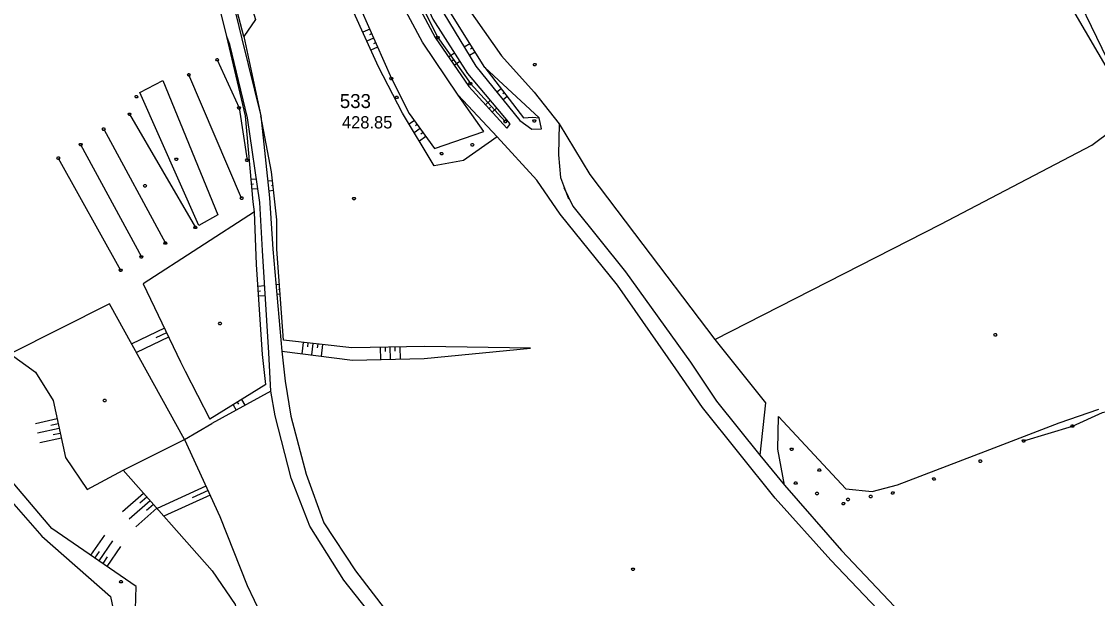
# Model space of a CAD drawing. Extents: x -664960 to -662754, y -993849 to -991145.
# Drawn here: x -663555.7 to -663293.4, y -993173.7 to -993033.1 of the extents above; entities that cross this region are included whole.
import ezdxf

# ---------------------------------------------------------------- set-up
doc = ezdxf.new("R2010")
doc.units = 0
for name, color, linetype in [('Vrstva 1', 7, 'Continuous'), ('Vrstva 13', 7, 'Continuous'), ('Vrstva 27', 7, 'Continuous'), ('Vrstva 63', 7, 'Continuous'), ('Vrstva 8', 7, 'Continuous')]:
    doc.layers.add(name, color=color, linetype=linetype)

msp = doc.modelspace()

# ---------------------------------------------------------------- linework, layer by layer
at = {"layer": 'Vrstva 13'}
for points in [[(-663430.387, -993043.291), (-663430.207, -993043.591), (-663430.387, -993043.891), (-663430.747, -993043.891), (-663430.927, -993043.591), (-663430.747, -993043.291), (-663430.387, -993043.291)], [(-663517.748, -993066.373), (-663517.568, -993066.673), (-663517.748, -993066.973), (-663518.108, -993066.973), (-663518.288, -993066.673), (-663518.108, -993066.373), (-663517.748, -993066.373)], [(-663525.362, -993072.832), (-663525.182, -993073.132), (-663525.362, -993073.432), (-663525.722, -993073.432), (-663525.902, -993073.132), (-663525.722, -993072.832), (-663525.362, -993072.832)], [(-663474.427, -993075.96), (-663474.247, -993076.26), (-663474.427, -993076.56), (-663474.787, -993076.56), (-663474.967, -993076.26), (-663474.787, -993075.96), (-663474.427, -993075.96)], [(-663507.072, -993106.416), (-663506.892, -993106.716), (-663507.072, -993107.016), (-663507.432, -993107.016), (-663507.612, -993106.716), (-663507.432, -993106.416), (-663507.072, -993106.416)], [(-663318.17, -993109.156), (-663317.99, -993109.456), (-663318.17, -993109.756), (-663318.53, -993109.756), (-663318.71, -993109.456), (-663318.53, -993109.156), (-663318.17, -993109.156)], [(-663535.22, -993125.181), (-663535.04, -993125.481), (-663535.22, -993125.781), (-663535.58, -993125.781), (-663535.76, -993125.481), (-663535.58, -993125.181), (-663535.22, -993125.181)], [(-663366.791, -993145.297), (-663366.611, -993145.597), (-663366.791, -993145.897), (-663367.151, -993145.897), (-663367.331, -993145.597), (-663367.151, -993145.297), (-663366.791, -993145.297)], [(-663406.456, -993166.312), (-663406.276, -993166.612), (-663406.456, -993166.912), (-663406.816, -993166.912), (-663406.996, -993166.612), (-663406.816, -993166.312), (-663406.456, -993166.312)]]:
    msp.add_lwpolyline(points, dxfattribs=at)
at = {"layer": 'Vrstva 27'}
msp.add_line((-663436.64, -993058.03), (-663437.38, -993059.1), dxfattribs=at)
for points in [[(-663488.658, -992771.319), (-663486.041, -992777.124), (-663484.479, -992778.312), (-663480.688, -992780.627), (-663479.797, -992784.051), (-663480.225, -992798.776), (-663480.106, -992812.528), (-663479.191, -992846.153), (-663478.672, -992868.89), (-663478.583, -992881.904), (-663478.082, -992895.396), (-663476.627, -992914.637), (-663474.815, -992928.231), (-663470.676, -992951.637), (-663468.34, -992962.956), (-663456.927, -993007.431), (-663447.138, -993029.424), (-663438.677, -993041.464), (-663430.737, -993050.315), (-663424.65, -993058.054), (-663424.821, -993065.561), (-663424.273, -993071.083), (-663422.364, -993076.277)], [(-663493.095, -992883.033), (-663492.196, -992861.424), (-663492.956, -992822.595), (-663492.609, -992797.023), (-663492.331, -992783.259), (-663491.101, -992775.678), (-663489.833, -992782.642), (-663491.019, -992797.262), (-663489.769, -992835.934), (-663490.477, -992858.663), (-663491.12, -992880.1), (-663489.906, -992896.409), (-663487.878, -992911.561), (-663485.118, -992929.166), (-663480.702, -992952.347), (-663470.868, -992991.635), (-663466.023, -993009.002), (-663455.437, -993032.516), (-663446.928, -993045.767), (-663436.64, -993058.03)], [(-663292.32, -993232.82), (-663314.09, -993212.62), (-663328.7, -993196.3), (-663343.76, -993179.73), (-663358.38, -993164.43), (-663372, -993149.25), (-663389.69, -993127.17), (-663396.18, -993117.78), (-663410.43, -993097.33), (-663424.37, -993080.01), (-663430.1, -993071.8), (-663439.74, -993061.19), (-663449.23, -993051.04), (-663457.96, -993038.08), (-663463.23, -993028.27), (-663471.77, -993006.86), (-663476.02, -992992.74), (-663480.89, -992974.93), (-663481.39, -992971.3), (-663486.69, -992951.1), (-663491.43, -992929.63), (-663493.61, -992914.38), (-663496.5, -992893.77)], [(-663490.26, -992913.59), (-663487.91, -992929.15), (-663483.47, -992949.71), (-663477.64, -992974.17), (-663473.27, -992991.48), (-663468.86, -993005.23), (-663460.26, -993026.75), (-663454.82, -993037.02), (-663446.62, -993048.94), (-663437.38, -993059.1)], [(-663525.07, -992922.44), (-663521.64, -992937.94), (-663518.46, -992961.72), (-663514.64, -992984.19), (-663509.85, -993004.83), (-663501.96, -993037.29), (-663497.29, -993056.07), (-663495.2, -993076.09), (-663494.44, -993088.61), (-663492.24, -993113.44), (-663491.4, -993120.78), (-663490.02, -993129.31), (-663486.29, -993143.39), (-663482, -993155.26), (-663474.22, -993166.96), (-663462.98, -993181.7), (-663450.36, -993195.84), (-663435.28, -993211.34), (-663418, -993227.21), (-663404.31, -993240.04), (-663391.6, -993253.92), (-663379.85, -993267.71)], [(-663381.88, -993269.82), (-663387.32, -993265.33), (-663393.79, -993257), (-663407.95, -993241.48), (-663421.02, -993229.28), (-663438.16, -993213.52), (-663452.44, -993198.54), (-663465.76, -993183.63), (-663477.14, -993169.29), (-663485.35, -993156.12), (-663489.97, -993144.37), (-663493.8, -993129.17), (-663494.9, -993123.17), (-663495.36, -993113.85), (-663496.9, -993088.93), (-663497.54, -993077.21), (-663500.56, -993056.55), (-663504.87, -993038.7), (-663505.62, -993036.77), (-663513.31, -993005.37), (-663518.03, -992984.98), (-663521.99, -992961.69), (-663525.31, -992938.73), (-663526.62, -992930.83)], [(-663452.727, -993031.168), (-663444.935, -993044.005), (-663434.228, -993057.192)], [(-663434.228, -993057.192), (-663431.273, -993059.365), (-663428.963, -993059.284), (-663429.498, -993056.55), (-663442.777, -993044.277), (-663451.02, -993031.047)], [(-663423.48, -993073.55), (-663421.28, -993078.11), (-663408.44, -993094.13), (-663392.6, -993116.09), (-663386.27, -993125.65), (-663375.681, -993138.823)], [(-663375.681, -993138.823), (-663369.729, -993146.08), (-663355.79, -993162.06), (-663341.44, -993177.26), (-663326.1, -993194.37), (-663310.82, -993210.78), (-663290.07, -993230.27), (-663283.91, -993235.59), (-663283.15, -993228.16)]]:
    msp.add_lwpolyline(points, dxfattribs=at)
at = {"layer": 'Vrstva 63'}
for p, q in [((-663470.8, -993034.977), (-663472.46, -993035.707)), ((-663470.317, -993036.075), (-663470.866, -993036.317)), ((-663501.47, -993036.75), (-663497.29, -993056.07)), ((-663469.834, -993037.174), (-663471.472, -993037.894)), ((-663469.351, -993038.272), (-663469.893, -993038.511)), ((-663446.381, -993038.493), (-663447.759, -993039.352)), ((-663468.868, -993039.371), (-663470.484, -993040.081)), ((-663451.577, -993041.734), (-663450.149, -993040.751)), ((-663445.112, -993040.53), (-663446.514, -993041.404)), ((-663445.746, -993039.511), (-663446.209, -993039.8)), ((-663450.897, -993042.723), (-663450.432, -993042.403)), ((-663450.217, -993043.711), (-663448.851, -993042.772)), ((-663502.02, -993076.15), (-663514.87, -993046.09)), ((-663438.756, -993049.486), (-663439.819, -993050.306)), ((-663438.023, -993050.436), (-663438.369, -993050.703)), ((-663438.023, -993050.436), (-663438.369, -993050.703)), ((-663437.29, -993051.386), (-663438.305, -993052.17)), ((-663437.29, -993051.386), (-663438.305, -993052.17)), ((-663442.572, -993053.391), (-663441.415, -993052.339)), ((-663441.765, -993054.279), (-663441.391, -993053.939)), ((-663440.957, -993055.166), (-663439.871, -993054.179)), ((-663529.33, -993055.69), (-663513.29, -993083.28)), ((-663459.906, -993057.225), (-663461.179, -993058.142)), ((-663535.6, -993059.32), (-663520.59, -993087.1)), ((-663458.504, -993059.173), (-663459.939, -993060.207)), ((-663459.205, -993058.199), (-663459.656, -993058.524)), ((-663457.102, -993061.122), (-663458.7, -993062.272)), ((-663457.803, -993060.148), (-663458.308, -993060.511)), ((-663541.25, -993063.1), (-663526.45, -993090.48)), ((-663546.7, -993066.39), (-663531.49, -993093.72)), ((-663499.705, -993071.512), (-663498.389, -993071.399)), ((-663499.602, -993072.708), (-663499.14, -993072.668)), ((-663494.455, -993071.902), (-663495.624, -993072.032)), ((-663494.323, -993073.095), (-663494.714, -993073.138)), ((-663499.499, -993073.903), (-663498.042, -993073.778)), ((-663494.19, -993074.287), (-663495.374, -993074.419)), ((-663526.01, -993097.07), (-663526.01, -993097.07)), ((-663498.033, -993097.589), (-663496.372, -993097.477)), ((-663497.952, -993098.787), (-663497.401, -993098.749)), ((-663492.793, -993097.18), (-663493.675, -993097.243)), ((-663492.707, -993098.377), (-663492.994, -993098.397)), ((-663497.872, -993099.984), (-663496.224, -993099.873)), ((-663492.622, -993099.574), (-663493.463, -993099.634)), ((-663520.842, -993107.877), (-663528.773, -993111.669)), ((-663520.325, -993108.96), (-663522.944, -993110.212)), ((-663519.807, -993110.042), (-663527.61, -993113.773)), ((-663487.046, -993111.308), (-663487.356, -993114.065)), ((-663485.853, -993111.442), (-663485.957, -993112.366)), ((-663484.661, -993111.576), (-663484.975, -993114.37)), ((-663483.468, -993111.711), (-663483.574, -993112.647)), ((-663482.276, -993111.845), (-663482.594, -993114.674)), ((-663465.849, -993112.488), (-663465.797, -993115.435)), ((-663464.649, -993112.467), (-663464.632, -993113.446)), ((-663463.449, -993112.446), (-663463.398, -993115.379)), ((-663468.248, -993112.53), (-663468.197, -993115.491)), ((-663467.049, -993112.509), (-663467.031, -993113.493)), ((-663496.08, -993121.57), (-663509.78, -993130.06)), ((-663494.9, -993123.17), (-663509.29, -993131.09)), ((-663502.046, -993125.267), (-663501.198, -993126.636)), ((-663504.086, -993126.532), (-663503.303, -993127.795)), ((-663503.066, -993125.899), (-663502.795, -993126.338)), ((-663546.972, -993129.971), (-663552.247, -993131.124)), ((-663546.46, -993132.315), (-663551.735, -993133.468)), ((-663546.716, -993131.143), (-663548.472, -993131.527)), ((-663515.89, -993134.97), (-663509.29, -993131.09)), ((-663545.947, -993134.66), (-663551.222, -993135.813)), ((-663546.203, -993133.488), (-663547.96, -993133.872)), ((-663510.701, -993146.343), (-663522.627, -993151.785)), ((-663525.897, -993148.104), (-663531.008, -993152.643)), ((-663525.1, -993149.001), (-663526.802, -993150.512)), ((-663509.704, -993148.527), (-663520.96, -993153.662)), ((-663510.202, -993147.435), (-663514.062, -993149.196)), ((-663524.303, -993149.898), (-663529.414, -993154.437)), ((-663522.709, -993151.693), (-663527.82, -993156.232)), ((-663523.506, -993150.795), (-663525.208, -993152.307)), ((-663538.742, -993163.188), (-663535.38, -993158.305)), ((-663536.765, -993164.549), (-663533.404, -993159.666)), ((-663537.754, -993163.869), (-663536.634, -993162.243)), ((-663534.788, -993165.91), (-663531.427, -993161.027)), ((-663535.777, -993165.23), (-663534.657, -993163.603))]:
    msp.add_line(p, q, dxfattribs=at)
for points in [[(-663284.547, -993055.601), (-663299.44, -993030.172), (-663309.766, -993014.643), (-663318.448, -993000.715), (-663328.04, -992979.81), (-663341.459, -992959.362), (-663349.326, -992940.508), (-663361.239, -992916.927), (-663363.985, -992907.073), (-663365.563, -992896.567), (-663365.153, -992888.878), (-663367.39, -992872.717), (-663367.977, -992865.006), (-663366.113, -992853.429)], [(-663502.72, -992895.66), (-663500.68, -992911.72), (-663499.46, -992928.5), (-663496.04, -992950.81), (-663489.58, -992971.15), (-663490.24, -992973.92), (-663484.12, -992998.39), (-663477.64, -993017.5), (-663472.94, -993030.11), (-663465.51, -993047.01), (-663461.14, -993055.51), (-663454.98, -993064.07), (-663443.01, -993059.86), (-663449.23, -993051.04)], [(-663488.98, -992912.94), (-663486.69, -992929.18), (-663482.79, -992948.58), (-663476.6, -992971.57), (-663472.24, -992991.59), (-663467.82, -993006.73), (-663460.34, -993024.66), (-663454.22, -993037), (-663446.26, -993048.23), (-663437.77, -993057.47)], [(-663528.28, -993190.19), (-663527.67, -993170.81), (-663548.24, -993156.65), (-663567.3, -993134.31), (-663574.62, -993124.52), (-663575.76, -993123.74), (-663583.3, -993106.69), (-663584.43, -993103.48), (-663591.54, -993086.62), (-663586.94, -993078.34), (-663586.28, -993073.08), (-663589.41, -993059.58), (-663591.86, -993055.15), (-663591.76, -993041.53), (-663588.44, -993036.54), (-663581.11, -993025.88), (-663583.2, -993018.84), (-663591.05, -993014.06), (-663610.46, -992999.53), (-663616.86, -992987.81), (-663623.87, -992975.97), (-663633.54, -992963.29)], [(-663439.74, -993061.19), (-663447.96, -993066.95), (-663455.1, -993068.27), (-663462.83, -993055.39), (-663468.65, -993044.14), (-663477.89, -993023.69), (-663486.03, -992998.86), (-663489.83, -992986.14), (-663509.79, -992996.09), (-663498.66, -993032.57), (-663501.47, -993036.75), (-663509.85, -993004.83)], [(-663246.904, -993114.369), (-663255.353, -993101.711), (-663256.984, -993088.158), (-663273.685, -993069.79), (-663284.547, -993055.601), (-663300.016, -993023.681), (-663309.766, -993014.643)], [(-663477.64, -993017.5), (-663472.94, -993030.11), (-663465.51, -993047.01)], [(-663496.08, -993121.57), (-663496.91, -993114.26), (-663498.39, -993092.29), (-663498.87, -993079.49), (-663499.23, -993077.04), (-663501.03, -993056.09), (-663505.62, -993036.77)], [(-663454.04, -993036.7), (-663453.86, -993037), (-663454.04, -993037.3), (-663454.4, -993037.3), (-663454.58, -993037), (-663454.4, -993036.7), (-663454.04, -993036.7)], [(-663507.79, -993042.09), (-663507.61, -993042.39), (-663507.79, -993042.69), (-663508.15, -993042.69), (-663508.33, -993042.39), (-663508.15, -993042.09), (-663507.79, -993042.09)], [(-663507.97, -993042.39), (-663502.64, -993054.16), (-663500.68, -993066.87)], [(-663442.777, -993044.277), (-663433.284, -993056.576), (-663431.053, -993056.394), (-663429.498, -993056.55)], [(-663514.69, -993045.79), (-663514.51, -993046.09), (-663514.69, -993046.39), (-663515.05, -993046.39), (-663515.23, -993046.09), (-663515.05, -993045.79), (-663514.69, -993045.79)], [(-663465.33, -993046.71), (-663465.15, -993047.01), (-663465.33, -993047.31), (-663465.69, -993047.31), (-663465.87, -993047.01), (-663465.69, -993046.71), (-663465.33, -993046.71)], [(-663526.78, -993050.43), (-663521.21, -993047.47), (-663507.81, -993080.19), (-663512.45, -993082.81), (-663526.78, -993050.43)], [(-663446.08, -993047.93), (-663445.9, -993048.23), (-663446.08, -993048.53), (-663446.44, -993048.53), (-663446.62, -993048.23), (-663446.44, -993047.93), (-663446.08, -993047.93)], [(-663527.47, -993051.11), (-663527.29, -993051.41), (-663527.47, -993051.71), (-663527.83, -993051.71), (-663528.01, -993051.41), (-663527.83, -993051.11), (-663527.47, -993051.11)], [(-663502.46, -993053.86), (-663502.28, -993054.16), (-663502.46, -993054.46), (-663502.82, -993054.46), (-663503, -993054.16), (-663502.82, -993053.86), (-663502.46, -993053.86)], [(-663529.15, -993055.39), (-663528.97, -993055.69), (-663529.15, -993055.99), (-663529.51, -993055.99), (-663529.69, -993055.69), (-663529.51, -993055.39), (-663529.15, -993055.39)], [(-663492.24, -993113.44), (-663474.97, -993115.65), (-663457.49, -993115.24), (-663431.634, -993112.752), (-663457.36, -993112.34), (-663475.13, -993112.65), (-663491.82, -993110.77), (-663493.41, -993088.56), (-663493.4, -993081.42), (-663494.7, -993069.69), (-663497.29, -993056.07)], [(-663437.59, -993057.17), (-663437.41, -993057.47), (-663437.59, -993057.77), (-663437.95, -993057.77), (-663438.13, -993057.47), (-663437.95, -993057.17), (-663437.59, -993057.17)], [(-663430.49, -993057.014), (-663430.31, -993057.314), (-663430.49, -993057.614), (-663430.85, -993057.614), (-663431.03, -993057.314), (-663430.85, -993057.014), (-663430.49, -993057.014)], [(-663386.718, -993110.575), (-663331.567, -993082.506), (-663294.803, -993063.252), (-663284.547, -993055.601)], [(-663535.42, -993059.02), (-663535.24, -993059.32), (-663535.42, -993059.62), (-663535.78, -993059.62), (-663535.96, -993059.32), (-663535.78, -993059.02), (-663535.42, -993059.02)], [(-663424.65, -993058.054), (-663417.136, -993070.372), (-663406.273, -993084.722), (-663386.718, -993110.575), (-663374.342, -993126.019), (-663375.681, -993138.823)], [(-663541.07, -993062.8), (-663540.89, -993063.1), (-663541.07, -993063.4), (-663541.43, -993063.4), (-663541.61, -993063.1), (-663541.43, -993062.8), (-663541.07, -993062.8)], [(-663453.11, -993065), (-663452.93, -993065.3), (-663453.11, -993065.6), (-663453.47, -993065.6), (-663453.65, -993065.3), (-663453.47, -993065), (-663453.11, -993065)], [(-663445.6, -993062.85), (-663445.42, -993063.15), (-663445.6, -993063.45), (-663445.96, -993063.45), (-663446.14, -993063.15), (-663445.96, -993062.85), (-663445.6, -993062.85)], [(-663546.52, -993066.09), (-663546.34, -993066.39), (-663546.52, -993066.69), (-663546.88, -993066.69), (-663547.06, -993066.39), (-663546.88, -993066.09), (-663546.52, -993066.09)], [(-663500.5, -993066.57), (-663500.32, -993066.87), (-663500.5, -993067.17), (-663500.86, -993067.17), (-663501.04, -993066.87), (-663500.86, -993066.57), (-663500.5, -993066.57)], [(-663588.73, -993072.01), (-663588.67, -993078.79), (-663591.54, -993086.62), (-663590.79, -993097.47), (-663587.28, -993107.16), (-663580.23, -993125.77), (-663578.42, -993128.41), (-663569.53, -993137.12), (-663550.67, -993158.56), (-663534, -993173.23), (-663531.62, -993184.53), (-663529.51, -993196.8), (-663524.27, -993210.22), (-663515.61, -993222.94), (-663503.03, -993237.27)], [(-663567.12, -993071.76), (-663567.81, -993074.85), (-663569.5, -993087.65), (-663569.75, -993094.71), (-663565.21, -993104.7), (-663558.45, -993114.09), (-663552.27, -993118.59), (-663547.96, -993125.45), (-663544.92, -993139.36), (-663539.64, -993147.19), (-663530.9, -993142.47), (-663509.15, -993166.96), (-663503.55, -993175.23), (-663501.36, -993184.63), (-663489.77, -993200.53), (-663484.02, -993206.52), (-663460.84, -993226.03), (-663453.96, -993246.94), (-663453.78, -993261.37), (-663437.09, -993283.52), (-663427.78, -993292.06), (-663412.1, -993308.96)], [(-663501.84, -993075.85), (-663501.66, -993076.15), (-663501.84, -993076.45), (-663502.2, -993076.45), (-663502.38, -993076.15), (-663502.2, -993075.85), (-663501.84, -993075.85)], [(-663498.87, -993079.49), (-663526.01, -993097.07), (-663516.92, -993116.08), (-663515.75, -993118.28), (-663509.78, -993130.06)], [(-663513.11, -993082.98), (-663512.93, -993083.28), (-663513.11, -993083.58), (-663513.47, -993083.58), (-663513.65, -993083.28), (-663513.47, -993082.98), (-663513.11, -993082.98)], [(-663520.41, -993086.8), (-663520.23, -993087.1), (-663520.41, -993087.4), (-663520.77, -993087.4), (-663520.95, -993087.1), (-663520.77, -993086.8), (-663520.41, -993086.8)], [(-663526.27, -993090.18), (-663526.09, -993090.48), (-663526.27, -993090.78), (-663526.63, -993090.78), (-663526.81, -993090.48), (-663526.63, -993090.18), (-663526.27, -993090.18)], [(-663531.31, -993093.42), (-663531.13, -993093.72), (-663531.31, -993094.02), (-663531.67, -993094.02), (-663531.85, -993093.72), (-663531.67, -993093.42), (-663531.31, -993093.42)], [(-663515.89, -993134.97), (-663534.18, -993101.89), (-663558.45, -993114.09)], [(-663311.407, -993135.342), (-663299.548, -993131.706), (-663292.235, -993128.405), (-663280.868, -993125.552), (-663246.904, -993114.369)], [(-663369.729, -993146.08), (-663371.325, -993137.333), (-663371.135, -993129.39), (-663354.75, -993146.972), (-663348.347, -993147.641), (-663342.206, -993146.002), (-663320.697, -993137.861), (-663302.753, -993130.937), (-663293.129, -993127.585)], [(-663299.368, -993131.406), (-663299.188, -993131.706), (-663299.368, -993132.006), (-663299.728, -993132.006), (-663299.908, -993131.706), (-663299.728, -993131.406), (-663299.368, -993131.406)], [(-663530.9, -993142.47), (-663515.89, -993134.97), (-663507.33, -993153.73), (-663500.64, -993170.55), (-663497.23, -993177.75), (-663487.76, -993192.96), (-663480.9, -993203.16), (-663460.24, -993223.43)], [(-663311.227, -993135.042), (-663311.047, -993135.342), (-663311.227, -993135.642), (-663311.587, -993135.642), (-663311.767, -993135.342), (-663311.587, -993135.042), (-663311.227, -993135.042)], [(-663367.779, -993137.071), (-663367.599, -993137.371), (-663367.779, -993137.671), (-663368.139, -993137.671), (-663368.319, -993137.371), (-663368.139, -993137.071), (-663367.779, -993137.071)], [(-663321.767, -993139.975), (-663321.587, -993140.275), (-663321.767, -993140.575), (-663322.127, -993140.575), (-663322.307, -993140.275), (-663322.127, -993139.975), (-663321.767, -993139.975)], [(-663361.044, -993142.118), (-663360.864, -993142.418), (-663361.044, -993142.718), (-663361.404, -993142.718), (-663361.584, -993142.418), (-663361.404, -993142.118), (-663361.044, -993142.118)], [(-663333.114, -993144.282), (-663332.934, -993144.582), (-663333.114, -993144.882), (-663333.474, -993144.882), (-663333.654, -993144.582), (-663333.474, -993144.282), (-663333.114, -993144.282)], [(-663361.603, -993147.835), (-663361.423, -993148.135), (-663361.603, -993148.435), (-663361.963, -993148.435), (-663362.143, -993148.135), (-663361.963, -993147.835), (-663361.603, -993147.835)], [(-663348.529, -993148.587), (-663348.349, -993148.887), (-663348.529, -993149.187), (-663348.889, -993149.187), (-663349.069, -993148.887), (-663348.889, -993148.587), (-663348.529, -993148.587)], [(-663343.137, -993147.703), (-663342.957, -993148.003), (-663343.137, -993148.303), (-663343.497, -993148.303), (-663343.677, -993148.003), (-663343.497, -993147.703), (-663343.137, -993147.703)], [(-663355.157, -993150.318), (-663354.977, -993150.618), (-663355.157, -993150.918), (-663355.517, -993150.918), (-663355.697, -993150.618), (-663355.517, -993150.318), (-663355.157, -993150.318)], [(-663354.041, -993149.296), (-663353.861, -993149.596), (-663354.041, -993149.896), (-663354.401, -993149.896), (-663354.581, -993149.596), (-663354.401, -993149.296), (-663354.041, -993149.296)], [(-663531.22, -993169.34), (-663531.04, -993169.64), (-663531.22, -993169.94), (-663531.58, -993169.94), (-663531.76, -993169.64), (-663531.58, -993169.34), (-663531.22, -993169.34)]]:
    msp.add_lwpolyline(points, dxfattribs=at)
at = {"layer": 'Vrstva 8'}
msp.add_lwpolyline([(-663464.06, -993051.29), (-663463.88, -993051.59), (-663464.06, -993051.89), (-663464.42, -993051.89), (-663464.6, -993051.59), (-663464.42, -993051.29), (-663464.06, -993051.29)], dxfattribs=at)

# ---------------------------------------------------------------- texts
at = {"layer": 'Vrstva 1'}
msp.add_text('533', height=3.4, dxfattribs=at).set_placement((-663478.075, -993054.177))
at = {"layer": 'Vrstva 63'}
msp.add_text('428.85', height=3, dxfattribs=at).set_placement((-663477.551, -993059.157))

doc.saveas('drawing.dxf')
